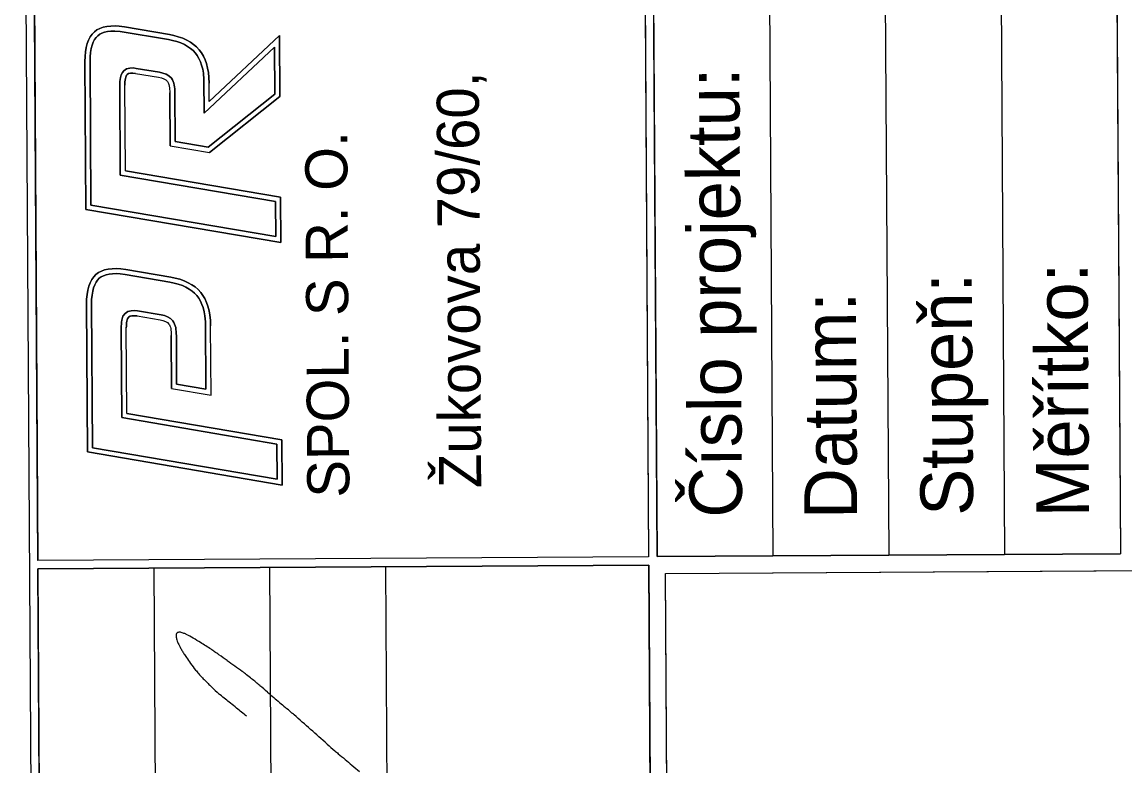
# Model space of a CAD drawing. Extents: x -735036 to -734743, y -1144813 to -1144181.
# Drawn here: x -734819.2 to -734769.45, y -1144255.42 to -1144221.87 of the extents above; entities that cross this region are included whole.
import ezdxf

# ---------------------------------------------------------------- set-up
doc = ezdxf.new("R2010")
doc.units = 0
doc.layers.add('000_rozpiska', color=7, linetype='Continuous')

# ---------------------------------------------------------------- blocks, each defined once
blk = doc.blocks.new('A$C2B726605')
at = {"layer": '000_rozpiska'}
for p, q in [((-8.894, 71.716), (-181.794, 71.716)), ((-8.894, 71.716), (-181.794, 71.716)), ((-63.424, 71.336), (-181.794, 71.336)), ((-63.424, 43.784), (-63.424, 71.336)), ((-8.894, 71.336), (-63.044, 71.336)), ((-63.044, 43.784), (-63.044, 71.336)), ((-59.709, 60.291), (-58.162, 69.071)), ((-58.164, 69.072), (-51.5, 69.072)), ((-48.767, 60.291), (-47.22, 69.071)), ((-47.222, 69.072), (-40.558, 69.072)), ((-56.434, 67.282), (-57.665, 60.291)), ((-56.434, 67.282), (-52.576, 67.282)), ((-49.947, 67.282), (-50.304, 65.256)), ((-45.492, 67.282), (-46.723, 60.291)), ((-45.492, 67.282), (-41.634, 67.282)), ((-39.005, 67.282), (-39.362, 65.256)), ((-52.042, 66.796), (-52.226, 65.755)), ((-41.1, 66.796), (-41.284, 65.755)), ((-63.424, 66.111), (-184.264, 66.111)), ((-55.325, 65.256), (-55.638, 63.481)), ((-55.325, 65.256), (-52.933, 65.256)), ((-44.383, 65.256), (-44.696, 63.481)), ((-44.383, 65.256), (-41.991, 65.256)), ((-55.638, 63.481), (-52.508, 63.481)), ((-42.191, 60.291), (-44.696, 63.481)), ((-42.389, 63.481), (-41.567, 63.481)), ((-39.439, 60.291), (-42.389, 63.481)), ((-63.424, 60.886), (-184.264, 60.886)), ((-57.665, 60.291), (-59.709, 60.291)), ((-46.723, 60.291), (-48.767, 60.291)), ((-39.439, 60.291), (-42.191, 60.291)), ((-63.424, 55.661), (-184.264, 55.661)), ((-63.424, 43.784), (-184.264, 43.784)), ((-184.264, 43.784), (-63.424, 43.784)), ((-6.424, 43.784), (-63.044, 43.784)), ((-63.044, 43.404), (-63.044, 22.504)), ((-6.424, 43.404), (-63.044, 43.404)), ((-183.884, 43.024), (-63.804, 43.024)), ((-63.804, 43.024), (-63.804, 6.804)), ((-6.424, 38.179), (-63.044, 38.179)), ((-6.424, 32.954), (-63.044, 32.954)), ((-6.424, 27.729), (-63.044, 27.729)), ((-6.424, 22.504), (-63.044, 22.504))]:
    blk.add_line(p, q, dxfattribs=at)
for points in [[(-181.794, 71.336), (-63.424, 71.336), (-63.424, 43.784)], [(-63.044, 43.784), (-63.044, 71.336), (-8.894, 71.336)], [(-63.424, 43.784), (-184.264, 43.784), (-184.264, 68.866)], [(-6.424, 68.866), (-6.424, 43.784), (-63.044, 43.784)], [(-50.687, 68.963), (-50.864, 69.011), (-51.061, 69.045), (-51.275, 69.066), (-51.5, 69.072), (-58.162, 69.072), (-59.709, 60.291), (-57.665, 60.291), (-56.434, 67.282), (-52.576, 67.282), (-52.505, 67.28), (-52.422, 67.276), (-52.344, 67.267), (-52.276, 67.256), (-52.217, 67.241), (-52.168, 67.222), (-52.127, 67.2), (-52.095, 67.174), (-52.054, 67.111), (-52.032, 67.026), (-52.029, 66.916), (-52.042, 66.796), (-52.226, 65.755), (-52.255, 65.629), (-52.298, 65.515), (-52.35, 65.426), (-52.415, 65.36), (-52.455, 65.336), (-52.502, 65.314), (-52.56, 65.295), (-52.624, 65.281), (-52.698, 65.269), (-52.772, 65.261), (-52.862, 65.257), (-52.933, 65.256), (-55.325, 65.256), (-55.638, 63.481), (-52.508, 63.481), (-52.255, 63.488), (-52.029, 63.509), (-51.827, 63.542), (-51.622, 63.593), (-51.452, 63.651), (-51.281, 63.729), (-51.133, 63.816), (-50.997, 63.915), (-50.866, 64.032), (-50.752, 64.167), (-50.649, 64.314), (-50.556, 64.477), (-50.474, 64.657), (-50.402, 64.856), (-50.345, 65.063), (-50.304, 65.256), (-49.947, 67.282), (-49.913, 67.52), (-49.899, 67.704), (-49.903, 67.903), (-49.918, 68.079), (-49.956, 68.245), (-50.007, 68.389), (-50.075, 68.522), (-50.163, 68.638), (-50.267, 68.739), (-50.389, 68.827), (-50.531, 68.902), (-50.687, 68.963)], [(-57.971, 68.844), (-51.507, 68.844), (-51.29, 68.838), (-51.091, 68.819), (-50.914, 68.788), (-50.758, 68.746), (-50.626, 68.695), (-50.51, 68.633), (-50.414, 68.564), (-50.335, 68.487), (-50.269, 68.4), (-50.217, 68.298), (-50.175, 68.181), (-50.144, 68.044), (-50.131, 67.891), (-50.127, 67.711), (-50.14, 67.545), (-50.172, 67.318), (-50.527, 65.303), (-50.567, 65.117), (-50.62, 64.925), (-50.685, 64.743), (-50.759, 64.581), (-50.842, 64.437), (-50.933, 64.306), (-51.03, 64.192), (-51.141, 64.092), (-51.258, 64.007), (-51.386, 63.932), (-51.537, 63.863), (-51.686, 63.812), (-51.873, 63.766), (-52.059, 63.735), (-52.334, 63.709), (-55.366, 63.709), (-55.134, 65.028), (-52.929, 65.028), (-52.855, 65.029), (-52.755, 65.034), (-52.668, 65.043), (-52.581, 65.056), (-52.499, 65.075), (-52.418, 65.102), (-52.348, 65.135), (-52.272, 65.18), (-52.168, 65.287), (-52.092, 65.417), (-52.036, 65.563), (-52.002, 65.71), (-51.816, 66.77), (-51.8, 66.907), (-51.805, 67.058), (-51.843, 67.204), (-51.923, 67.328), (-52.052, 67.434), (-52.229, 67.479), (-52.312, 67.493), (-52.404, 67.503), (-52.497, 67.508), (-52.57, 67.51), (-56.625, 67.51), (-57.857, 60.519), (-59.437, 60.519), (-57.971, 68.844)], [(-50.144, 68.044), (-50.175, 68.181), (-50.217, 68.298), (-50.269, 68.4), (-50.335, 68.487), (-50.414, 68.564), (-50.51, 68.633), (-50.626, 68.695), (-50.758, 68.746), (-50.914, 68.788), (-51.091, 68.819), (-51.29, 68.838), (-51.507, 68.844), (-57.971, 68.844), (-59.437, 60.519), (-57.857, 60.519), (-56.625, 67.51), (-52.57, 67.51), (-52.497, 67.508), (-52.404, 67.503), (-52.312, 67.493), (-52.229, 67.479), (-52.052, 67.434), (-51.923, 67.328), (-51.843, 67.204), (-51.805, 67.058), (-51.8, 66.907), (-51.816, 66.77), (-52.002, 65.71), (-52.036, 65.563), (-52.092, 65.417), (-52.168, 65.287), (-52.272, 65.18), (-52.348, 65.135), (-52.418, 65.102), (-52.499, 65.075), (-52.581, 65.056), (-52.668, 65.043), (-52.755, 65.034), (-52.855, 65.029), (-52.929, 65.028), (-55.134, 65.028), (-55.366, 63.709), (-52.334, 63.709), (-52.059, 63.735), (-51.873, 63.766), (-51.686, 63.812), (-51.537, 63.863), (-51.386, 63.932), (-51.258, 64.007), (-51.141, 64.092), (-51.03, 64.192), (-50.933, 64.306), (-50.842, 64.437), (-50.759, 64.581), (-50.685, 64.743), (-50.62, 64.925), (-50.567, 65.117), (-50.527, 65.303), (-50.172, 67.318), (-50.14, 67.545), (-50.127, 67.711), (-50.131, 67.891), (-50.144, 68.044)], [(-56.625, 67.51), (-57.857, 60.519), (-59.437, 60.519), (-57.971, 68.844), (-51.507, 68.844), (-51.29, 68.838), (-51.091, 68.819), (-50.914, 68.788), (-50.758, 68.746), (-50.626, 68.695), (-50.51, 68.633), (-50.414, 68.564), (-50.335, 68.487), (-50.269, 68.4), (-50.217, 68.298), (-50.175, 68.181), (-50.144, 68.044), (-50.131, 67.891), (-50.127, 67.711), (-50.14, 67.545), (-50.172, 67.318), (-50.527, 65.303), (-50.567, 65.117), (-50.62, 64.925), (-50.685, 64.743), (-50.759, 64.581), (-50.842, 64.437), (-50.933, 64.306), (-51.03, 64.192), (-51.141, 64.092), (-51.258, 64.007), (-51.386, 63.932), (-51.537, 63.863), (-51.686, 63.812), (-51.873, 63.766), (-52.059, 63.735), (-52.334, 63.709), (-55.366, 63.709), (-55.134, 65.028), (-52.929, 65.028), (-52.855, 65.029), (-52.755, 65.034), (-52.668, 65.043), (-52.581, 65.056), (-52.499, 65.075), (-52.418, 65.102), (-52.348, 65.135), (-52.272, 65.18), (-52.168, 65.287), (-52.092, 65.417), (-52.036, 65.563), (-52.002, 65.71), (-51.816, 66.77), (-51.8, 66.907), (-51.805, 67.058), (-51.843, 67.204), (-51.923, 67.328), (-52.052, 67.434), (-52.229, 67.479), (-52.312, 67.493), (-52.404, 67.503), (-52.497, 67.508), (-52.57, 67.51), (-56.625, 67.51)], [(-51.5, 69.072), (-51.275, 69.066), (-51.061, 69.045), (-50.864, 69.011), (-50.687, 68.963), (-50.531, 68.902), (-50.389, 68.827), (-50.267, 68.739), (-50.163, 68.638), (-50.075, 68.522), (-50.007, 68.389), (-49.956, 68.245), (-49.918, 68.079), (-49.903, 67.903), (-49.899, 67.704), (-49.913, 67.52), (-49.947, 67.282)], [(-38.971, 67.52), (-38.957, 67.704), (-38.961, 67.903), (-38.976, 68.079), (-39.014, 68.245), (-39.065, 68.389), (-39.133, 68.522), (-39.221, 68.638), (-39.325, 68.739), (-39.447, 68.827), (-39.589, 68.902), (-39.745, 68.963), (-39.922, 69.011), (-40.119, 69.045), (-40.333, 69.066), (-40.558, 69.072), (-47.22, 69.072), (-48.767, 60.291), (-46.723, 60.291), (-45.492, 67.282), (-41.634, 67.282), (-41.563, 67.28), (-41.48, 67.276), (-41.402, 67.267), (-41.334, 67.256), (-41.275, 67.241), (-41.226, 67.222), (-41.185, 67.2), (-41.153, 67.174), (-41.112, 67.111), (-41.09, 67.026), (-41.087, 66.916), (-41.1, 66.796), (-41.284, 65.755), (-41.313, 65.629), (-41.356, 65.515), (-41.408, 65.426), (-41.473, 65.36), (-41.513, 65.336), (-41.56, 65.314), (-41.618, 65.295), (-41.682, 65.281), (-41.756, 65.269), (-41.83, 65.261), (-41.92, 65.257), (-41.991, 65.256), (-44.383, 65.256), (-44.696, 63.481), (-42.191, 60.291), (-39.439, 60.291), (-42.389, 63.481), (-41.567, 63.481), (-41.313, 63.488), (-41.087, 63.509), (-40.885, 63.542), (-40.68, 63.593), (-40.51, 63.651), (-40.339, 63.729), (-40.191, 63.816), (-40.055, 63.915), (-39.924, 64.032), (-39.81, 64.167), (-39.707, 64.314), (-39.614, 64.477), (-39.532, 64.657), (-39.46, 64.856), (-39.403, 65.063), (-39.362, 65.256), (-39.005, 67.282), (-38.971, 67.52)], [(-45.683, 67.51), (-46.915, 60.519), (-48.495, 60.519), (-47.029, 68.844), (-40.565, 68.844), (-40.348, 68.838), (-40.149, 68.819), (-39.972, 68.788), (-39.817, 68.746), (-39.684, 68.695), (-39.568, 68.633), (-39.472, 68.564), (-39.393, 68.487), (-39.327, 68.4), (-39.275, 68.298), (-39.233, 68.181), (-39.202, 68.044), (-39.189, 67.891), (-39.185, 67.711), (-39.203, 67.472), (-39.585, 65.303), (-39.625, 65.117), (-39.678, 64.925), (-39.743, 64.743), (-39.817, 64.581), (-39.9, 64.437), (-39.991, 64.306), (-40.088, 64.192), (-40.199, 64.092), (-40.316, 64.007), (-40.444, 63.932), (-40.595, 63.863), (-40.744, 63.812), (-40.931, 63.766), (-41.117, 63.735), (-41.392, 63.709), (-42.91, 63.709), (-39.96, 60.519), (-42.08, 60.519), (-44.454, 63.542), (-44.192, 65.028), (-41.987, 65.028), (-41.913, 65.029), (-41.813, 65.034), (-41.726, 65.043), (-41.639, 65.056), (-41.557, 65.075), (-41.476, 65.102), (-41.406, 65.135), (-41.33, 65.18), (-41.226, 65.287), (-41.15, 65.417), (-41.094, 65.563), (-41.06, 65.71), (-40.874, 66.77), (-40.858, 66.907), (-40.863, 67.058), (-40.901, 67.204), (-40.981, 67.328), (-41.057, 67.39), (-41.162, 67.447), (-41.287, 67.479), (-41.37, 67.493), (-41.462, 67.503), (-41.555, 67.508), (-41.628, 67.51), (-45.683, 67.51)], [(-39.275, 68.298), (-39.327, 68.4), (-39.393, 68.487), (-39.472, 68.564), (-39.568, 68.633), (-39.684, 68.695), (-39.817, 68.746), (-39.972, 68.788), (-40.149, 68.819), (-40.348, 68.838), (-40.565, 68.844), (-47.029, 68.844), (-48.495, 60.519), (-46.915, 60.519), (-45.683, 67.51), (-41.628, 67.51), (-41.555, 67.508), (-41.462, 67.503), (-41.37, 67.493), (-41.287, 67.479), (-41.162, 67.447), (-41.057, 67.39), (-40.981, 67.328), (-40.901, 67.204), (-40.863, 67.058), (-40.858, 66.907), (-40.874, 66.77), (-41.06, 65.71), (-41.094, 65.563), (-41.15, 65.417), (-41.226, 65.287), (-41.33, 65.18), (-41.406, 65.135), (-41.476, 65.102), (-41.557, 65.075), (-41.639, 65.056), (-41.726, 65.043), (-41.813, 65.034), (-41.913, 65.029), (-41.987, 65.028), (-44.192, 65.028), (-44.454, 63.542), (-42.08, 60.519), (-39.96, 60.519), (-42.91, 63.709), (-41.392, 63.709), (-41.117, 63.735), (-40.931, 63.766), (-40.744, 63.812), (-40.595, 63.863), (-40.444, 63.932), (-40.316, 64.007), (-40.199, 64.092), (-40.088, 64.192), (-39.991, 64.306), (-39.9, 64.437), (-39.817, 64.581), (-39.743, 64.743), (-39.678, 64.925), (-39.625, 65.117), (-39.585, 65.303), (-39.203, 67.472), (-39.185, 67.711), (-39.189, 67.891), (-39.202, 68.044), (-39.233, 68.181), (-39.275, 68.298)], [(-45.683, 67.51), (-46.915, 60.519), (-48.495, 60.519), (-47.029, 68.844), (-40.565, 68.844), (-40.348, 68.838), (-40.149, 68.819), (-39.972, 68.788), (-39.817, 68.746), (-39.684, 68.695), (-39.568, 68.633), (-39.472, 68.564), (-39.393, 68.487), (-39.327, 68.4), (-39.275, 68.298), (-39.233, 68.181), (-39.202, 68.044), (-39.189, 67.891), (-39.185, 67.711), (-39.203, 67.472), (-39.585, 65.303), (-39.625, 65.117), (-39.678, 64.925), (-39.743, 64.743), (-39.817, 64.581), (-39.9, 64.437), (-39.991, 64.306), (-40.088, 64.192), (-40.199, 64.092), (-40.316, 64.007), (-40.444, 63.932), (-40.595, 63.863), (-40.744, 63.812), (-40.931, 63.766), (-41.117, 63.735), (-41.392, 63.709), (-42.91, 63.709), (-39.96, 60.519), (-42.08, 60.519), (-44.454, 63.542), (-44.192, 65.028), (-41.987, 65.028), (-41.913, 65.029), (-41.813, 65.034), (-41.726, 65.043), (-41.639, 65.056), (-41.557, 65.075), (-41.476, 65.102), (-41.406, 65.135), (-41.33, 65.18), (-41.226, 65.287), (-41.15, 65.417), (-41.094, 65.563), (-41.06, 65.71), (-40.874, 66.77), (-40.858, 66.907), (-40.863, 67.058), (-40.901, 67.204), (-40.981, 67.328), (-41.057, 67.39), (-41.162, 67.447), (-41.287, 67.479), (-41.37, 67.493), (-41.462, 67.503), (-41.555, 67.508), (-41.628, 67.51), (-45.683, 67.51)], [(-40.558, 69.072), (-40.333, 69.066), (-40.119, 69.045), (-39.922, 69.011), (-39.745, 68.963), (-39.589, 68.902), (-39.447, 68.827), (-39.325, 68.739), (-39.221, 68.638), (-39.133, 68.522), (-39.065, 68.389), (-39.014, 68.245), (-38.976, 68.079), (-38.961, 67.903), (-38.957, 67.704), (-38.971, 67.52), (-39.005, 67.282)], [(-52.217, 67.241), (-52.276, 67.256), (-52.344, 67.267), (-52.422, 67.276), (-52.505, 67.28), (-52.576, 67.282)], [(-52.042, 66.796), (-52.029, 66.916), (-52.032, 67.026), (-52.054, 67.111), (-52.095, 67.174), (-52.127, 67.2), (-52.168, 67.222), (-52.217, 67.241)], [(-41.275, 67.241), (-41.334, 67.256), (-41.402, 67.267), (-41.48, 67.276), (-41.563, 67.28), (-41.634, 67.282)], [(-41.1, 66.796), (-41.087, 66.916), (-41.09, 67.026), (-41.112, 67.111), (-41.153, 67.174), (-41.185, 67.2), (-41.226, 67.222), (-41.275, 67.241)], [(-52.226, 65.755), (-52.255, 65.629), (-52.298, 65.515), (-52.35, 65.426), (-52.415, 65.36), (-52.455, 65.336), (-52.502, 65.314), (-52.56, 65.295), (-52.624, 65.281), (-52.698, 65.269), (-52.772, 65.261), (-52.862, 65.257), (-52.933, 65.256)], [(-41.284, 65.755), (-41.313, 65.629), (-41.356, 65.515), (-41.408, 65.426), (-41.473, 65.36), (-41.513, 65.336), (-41.56, 65.314), (-41.618, 65.295), (-41.682, 65.281), (-41.756, 65.269), (-41.83, 65.261), (-41.92, 65.257), (-41.991, 65.256)], [(-50.304, 65.256), (-50.345, 65.063), (-50.402, 64.856), (-50.474, 64.657), (-50.556, 64.477), (-50.649, 64.314), (-50.752, 64.167), (-50.866, 64.032), (-50.997, 63.915), (-51.133, 63.816), (-51.281, 63.729), (-51.452, 63.651), (-51.622, 63.593), (-51.827, 63.542), (-52.029, 63.509), (-52.255, 63.488), (-52.508, 63.481)], [(-39.362, 65.256), (-39.403, 65.063), (-39.46, 64.856), (-39.532, 64.657), (-39.614, 64.477), (-39.707, 64.314), (-39.81, 64.167), (-39.924, 64.032), (-40.055, 63.915), (-40.191, 63.816), (-40.339, 63.729), (-40.51, 63.651), (-40.68, 63.593), (-40.885, 63.542), (-41.087, 63.509), (-41.313, 63.488), (-41.567, 63.481)], [(-63.044, 22.504), (-63.044, 43.404), (-6.424, 43.404), (-6.424, 22.504), (-63.044, 22.504)], [(-183.884, 8.894), (-183.884, 43.024), (-63.804, 43.024), (-63.804, 6.804)]]:
    blk.add_lwpolyline(points, dxfattribs=at)
for s, height, p in [('SPOL. S R. O.', 1.9, (-60.29, 57.265)), ('Žukovova 79/60, ', 1.9, (-59.898, 51.316)), ('Číslo projektu:', 2.375, (-61.304, 39.558)), ('Datum:', 2.375, (-61.395, 34.367)), ('Stupeň:', 2.375, (-61.284, 29.133)), ('Měřítko:', 2.375, (-61.378, 23.906))]:
    blk.add_text(s, height=height, dxfattribs=at).set_placement(p)
blk = doc.blocks.new('Vodnansky')
at = {"layer": '000_rozpiska'}
for centre, radius, start, end in [((33.421, 3.793), 6.698, 122.3426, 124.2098), ((32.339, 5.501), 4.676, 120.1722, 122.3426), ((32.368, 5.451), 4.734, 118.015, 120.1722), ((31.187, 7.671), 2.219, 114.0617, 118.015), ((31.415, 7.161), 2.778, 110.5285, 114.0617), ((30.922, 8.476), 1.373, 105.9368, 110.5285), ((30.714, 9.206), 0.615, 99.071, 105.9368), ((30.663, 9.522), 0.295, 91.7892, 99.071), ((30.681, 8.967), 0.849, 87.5025, 91.7892), ((30.706, 9.54), 0.276, 75.9718, 87.5025), ((29.474, 10.008), 1.445, 332.4981, 338.4462), ((30.744, 9.693), 0.118, 58.2999, 75.9718), ((30.775, 9.744), 0.0579, 29.4928, 58.2999), ((30.124, 9.751), 0.746, 338.4462, 346.7254), ((30.637, 9.666), 0.217, 14.7156, 29.4928), ((30.54, 9.641), 0.317, 1.2743, 14.7156), ((30.586, 9.642), 0.271, 346.7254, 1.2743), ((31.348, 5.927), 3.755, 127.5601, 131.1576), ((35.488, 0.543), 10.547, 125.4138, 127.5601), ((38.712, -3.99), 16.109, 124.2098, 125.4138), ((22.597, 13.633), 9.219, 327.3501, 329.86), ((23.353, 13.194), 8.345, 329.86, 332.4981), ((43.563, -6.858), 21.439, 133.9214, 135.2837), ((32.305, 4.832), 5.209, 131.1576, 133.9214), ((-9.671, 34.309), 47.543, 326.6355, 327.3501), ((29.118, 6.809), 1.555, 136.0545, 139.7224), ((53.331, -16.53), 35.185, 135.2837, 136.0545), ((-8.399, 35.306), 47.058, 324.2166, 324.5251), ((25.484, 11.16), 5.451, 324.5251, 326.6355), ((-103.222, 113.841), 168.649, 320.80219, 321.01297), ((31.364, 4.906), 4.499, 139.7224, 141.013), ((-88.457, 92.923), 145.693, 323.70868, 324.05473), ((-108.895, 107.742), 170.939, 324.05473, 324.21659), ((-63.693, 82.408), 118.153, 320.02436, 320.31946), ((-6.744, 35.161), 44.157, 320.3195, 320.8022), ((22.512, 11.314), 7.945, 320.3663, 322.5356), ((18.755, 14.192), 12.678, 322.5356, 323.7087), ((-171.142, 178.591), 263.846, 319.00098, 319.10323), ((10.583, 21.194), 23.435, 319.1032, 320.3663), ((163.875, -112.624), 180.048, 139.00098, 139.12475), ((246.391, -184.04), 289.177, 139.12475, 139.26937), ((-481.073, 454.615), 678.878, 318.351181, 318.439698), ((13.415, 16.2), 18.025, 318.4397, 318.9829), ((-28.601, 52.747), 73.712, 318.98294, 319.26937), ((-40.552, 62.83), 89.34, 317.67719, 318.35118), ((39.107, -9.712), 18.399, 137.6772, 139.1624), ((416.137, -331.482), 514.069, 139.53278, 139.62746), ((50.605, -19.65), 33.597, 139.1624, 139.5328), ((230.678, -173.797), 270.636, 139.62746, 139.72735)]:
    blk.add_arc(centre, radius, start, end, dxfattribs=at)

msp = doc.modelspace()

# ---------------------------------------------------------------- block references
at = {"layer": '000_rozpiska', "rotation": 90.35414249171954}
msp.add_blockref('A$C2B726605', (-734747.538, -1144182.67), dxfattribs=at)
at = {"layer": '000_rozpiska', "xscale": 0.9499999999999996, "yscale": 0.9499999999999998, "rotation": 90.35414249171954}
msp.add_blockref('Vodnansky', (-734802.741, -1144278.647), dxfattribs=at)

doc.saveas('drawing.dxf')
